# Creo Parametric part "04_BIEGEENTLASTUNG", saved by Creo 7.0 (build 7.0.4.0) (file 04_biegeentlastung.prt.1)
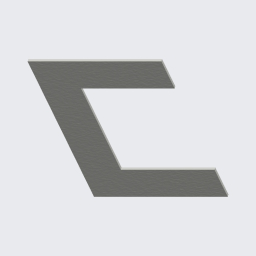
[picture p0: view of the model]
Units: millimeter Kilogram Sec (mmKs); MM, KILOGRAM, SECS
Materials in the file: S235JRG2

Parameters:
  SMT_PART_BEND_ALLOW_FACTOR_TYPE = "Y FACTOR"
  SMT_DFLT_RADIUS_SIDE = "Inside"
  SMT_DFLT_CRNR_REL_TYPE = "V Notch"
  SMT_DFLT_CRNR_REL_DEPTH_TYPE = "Blind"
  SMT_DFLT_BEND_REL_TYPE = "Rip"
  SMT_DFLT_BEND_REL_DEPTH_TYPE = "Up to Bend"
  SMT_DFLT_EDGE_TREA_TYPE = "Open"
  PTC_MATERIAL_NAME = "S235JRG2"
  BENENNUNG = "XXX"
  DATUM = "XX.XX.XX"
  ERSTELLER = "ARINDA"
  TEILETYP = "Fertigungsteil"
  SELECT_EN_NAME = "S235JRG2"
  SELECT_DIN_NAME = "RSt37-2"
  SELECT_DIN_NUMBER = "1.0038"
  SELECT_ASTM_NAME = "A 283 M Grade 2"
  MATERIAL_GROUP = "ME_ST_Baustahl"
  STANDARD_EN_DELIVERYSPEC = "DIN EN 10025"
  STANDARD_DIN_DELIVERYSPEC = "DIN 17100"

Other parameters: SMT_THICKNESS, SMT_PART_BEND_ALLOWANCE_FACTOR, SMT_UPDATE_BEND_ALLOW_INFO, SMT_DFLT_BEND_RADIUS, SMT_DFLT_BEND_ANGLE, SMT_DFLT_CRNR_REL_WIDTH, SMT_DFLT_CRNR_REL_DEPTH, SMT_DFLT_BEND_REL_WIDTH, SMT_DFLT_BEND_REL_DEPTH, SMT_DFLT_BEND_REL_ANGLE, SMT_GAP, SMT_DFLT_EDGE_TREA_WIDTH, SMT_DFLT_MITER_CUT_WIDTH, SMT_DFLT_MITER_CUT_OFFSET, MASSE, SMT_DFLT_BEND_REL_LENGTH

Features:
  1. coordinate system
  2. datum plane "DTM1", "T_RECHTS_Y-Z"
  3. datum plane "DTM2", "T_OBEN_X-Z"
  4. datum plane "DTM3", "T_VORNE_X-Y"
  5. datum axis "A_1"
  6. datum axis "A_2"
  7. datum axis "A_3"
  8. fill "Planar 1(Erste Lasche)"

Other named items: T_BASIS, A_X-ACHSE, A_Y-ACHSE, A_Z-ACHSE

Layers: 00_STD-ACHSEN, 00_STD-EBENEN, 00_STD-KOORDSYS, SAMMELFLÄCHEN, VOLUMENGEOMETRIE

Surfaces: 10 plane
